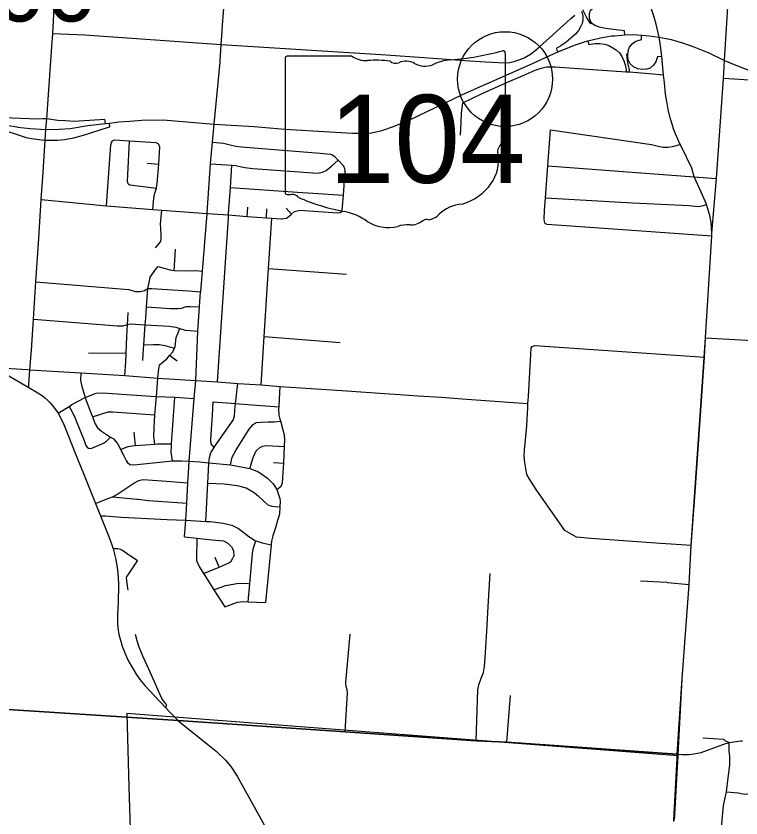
# Model space of a CAD drawing. Extents: x 1659811 to 1934326, y 644115 to 934867.
# Drawn here: x 1837325 to 1848780, y 687199 to 699875 of the extents above; entities that cross this region are included whole.
import ezdxf

# ---------------------------------------------------------------- set-up
doc = ezdxf.new("R2010")
doc.units = 0
for name, color, linetype in [('Default', 7, 'Continuous'), ('GM_X_City_Street', 7, 'Continuous'), ('GM_X_Corporation', 7, 'Continuous'), ('GM_X_County_Road', 7, 'Continuous'), ('GM_X_Interchange_Ramps', 7, 'Continuous'), ('GM_X_State_Route', 7, 'Continuous'), ('GM_X_State_Shield', 7, 'Continuous'), ('GM_X_Township', 7, 'Continuous')]:
    doc.layers.add(name, color=color, linetype=linetype)

msp = doc.modelspace()

# ---------------------------------------------------------------- linework, layer by layer
at = {"layer": 'Default'}
msp.add_circle((1845052, 698878), 750, dxfattribs=at)
at = {"layer": 'GM_X_City_Street'}
for points in [[(1840580, 699632), (1840586, 699731), (1840650, 700535), (1840697, 701240), (1840719, 701531), (1840765, 702254), (1840776, 702431), (1840844, 703924), (1840845, 703934), (1840845, 703937)], [(1837907, 699600), (1837933, 700105), (1837959, 700479), (1837971, 700637), (1837972, 700651)], [(1847992, 691508), (1848048, 692200), (1848097, 692948), (1848203, 694483), (1848221, 694789), (1848318, 696401), (1848321, 696445), (1848310, 696612), (1848289, 696722), (1848236, 696898), (1848234, 696903), (1848131, 697138), (1848040, 697335), (1848004, 697469), (1847840, 697807), (1847820, 697845), (1847746, 698014), (1847716, 698093), (1847691, 698166), (1847661, 698268), (1847628, 698400), (1847607, 698522), (1847590, 698642), (1847572, 698819), (1847558, 698947), (1847530, 699238), (1847515, 699368), (1847504, 699443), (1847487, 699540), (1847436, 699770), (1847403, 699874), (1847339, 700063)], [(1844738, 699151), (1844850, 699144), (1844944, 699139), (1845048, 699135), (1845128, 699143), (1845211, 699161), (1845287, 699186), (1845356, 699215), (1845456, 699275), (1845522, 699324), (1845597, 699389), (1845752, 699530), (1845977, 699730), (1846091, 699834), (1846156, 699888)], [(1837809, 698250), (1837888, 699392), (1837907, 699600)], [(1837907, 699600), (1838413, 699580), (1840566, 699427), (1843171, 699261), (1843771, 699218), (1844419, 699173), (1844738, 699151)], [(1840566, 699427), (1840580, 699632)], [(1840552, 699166), (1840566, 699427)], [(1840165, 694117), (1840200, 694896), (1840226, 695280), (1840242, 695515), (1840243, 695519), (1840269, 695842), (1840344, 696756), (1840345, 696765), (1840396, 697539), (1840397, 697546), (1840429, 697881), (1840456, 698168), (1840551, 699148), (1840552, 699166)], [(1844348, 697993), (1844357, 698196), (1844364, 698341), (1844383, 698503), (1844690, 698650), (1845091, 698828), (1845340, 698936), (1845530, 699021), (1845621, 699053), (1845705, 699072)], [(1845705, 699072), (1845766, 699074), (1845839, 699074), (1846966, 698995), (1847016, 698991)], [(1847016, 698991), (1847329, 698966), (1847558, 698947)], [(1837783, 697914), (1837797, 698083), (1837809, 698250)], [(1845683, 696603), (1845670, 696663), (1845676, 696803), (1845690, 697002), (1845728, 697506), (1845770, 698077)], [(1845770, 698077), (1847365, 697845), (1847473, 697819), (1847553, 697804), (1847631, 697805), (1847697, 697812), (1847820, 697845)], [(1837525, 694003), (1837525, 694057), (1837543, 694284), (1837567, 694593), (1837600, 695085), (1837637, 695675), (1837683, 696361), (1837720, 696974), (1837752, 697400), (1837783, 697914)], [(1838754, 696874), (1838824, 697841), (1838832, 697879), (1838849, 697903)], [(1838849, 697903), (1838883, 697918), (1839115, 697904), (1839535, 697879), (1839575, 697856)], [(1839097, 697225), (1839086, 697262), (1839089, 697364), (1839115, 697904)], [(1839488, 696819), (1839502, 696995), (1839519, 697073), (1839543, 697155), (1839545, 697159), (1839556, 697229), (1839579, 697533), (1839593, 697719), (1839598, 697804), (1839575, 697856)], [(1840429, 697881), (1840602, 697865), (1840710, 697839), (1840798, 697816), (1840886, 697809), (1842130, 697710), (1842288, 697690)], [(1842473, 696787), (1842477, 696809), (1842484, 696865), (1842498, 697045), (1842526, 697430), (1842521, 697458), (1842506, 697502), (1842413, 697599), (1842369, 697644), (1842314, 697681), (1842288, 697690)], [(1840396, 697539), (1840736, 697519), (1840797, 697515), (1840885, 697494), (1840941, 697479), (1841067, 697463), (1842091, 697392), (1842168, 697405), (1842226, 697436), (1842317, 697509), (1842413, 697599)], [(1839398, 697548), (1839579, 697533)], [(1840680, 696688), (1840683, 696731), (1840684, 696752), (1840712, 697164), (1840736, 697519)], [(1845728, 697506), (1848040, 697335), (1848393, 697309)], [(1839097, 697225), (1839121, 697209), (1839543, 697155)], [(1840712, 697164), (1841773, 697092), (1842498, 697045)], [(1837720, 696974), (1838754, 696874), (1839488, 696819), (1839628, 696809), (1840344, 696756), (1840346, 696756), (1840683, 696731), (1840978, 696709), (1841280, 696686), (1841366, 696680), (1841516, 696669), (1841532, 696671)], [(1845690, 697002), (1847065, 696923), (1847964, 696878), (1848102, 696864), (1848188, 696880), (1848236, 696898)], [(1839531, 696209), (1839606, 696304), (1839617, 696344), (1839618, 696406), (1839613, 696520), (1839610, 696586), (1839628, 696809)], [(1840978, 696709), (1840986, 696853)], [(1841280, 696686), (1841290, 696830)], [(1841532, 696671), (1841562, 696677), (1841598, 696683), (1841667, 696734), (1841677, 696743), (1841724, 696788), (1841810, 696807), (1842407, 696766), (1842445, 696771), (1842473, 696787)], [(1841677, 696743), (1841593, 696840)], [(1840510, 694093), (1840680, 696688)], [(1841198, 694046), (1841246, 694808), (1841294, 695559), (1841315, 695886), (1841366, 696680)], [(1845683, 696603), (1845714, 696584), (1845943, 696569), (1848318, 696401)], [(1839837, 696093), (1839837, 696093), (1839843, 696188)], [(1839824, 695855), (1839837, 696093)], [(1839336, 694532), (1839336, 694532), (1839346, 694680), (1839367, 694996), (1839374, 695100), (1839386, 695279), (1839406, 695569), (1839429, 695661), (1839446, 695747), (1839534, 695876), (1839573, 695919)], [(1839573, 695919), (1839660, 695890), (1839782, 695856), (1839824, 695855), (1840050, 695850), (1840162, 695852), (1840269, 695842)], [(1841315, 695886), (1842547, 695797)], [(1837637, 695675), (1838977, 695561), (1839107, 695553), (1839208, 695520), (1839247, 695519), (1839257, 695519)], [(1839257, 695519), (1839290, 695519), (1839353, 695538), (1839406, 695569), (1839471, 695568), (1840052, 695531), (1840242, 695515)], [(1839386, 695279), (1839761, 695255), (1839885, 695251), (1839943, 695258), (1840008, 695283), (1840082, 695286), (1840226, 695280)], [(1839091, 695083), (1839096, 695188)], [(1837600, 695085), (1838927, 694977), (1838940, 694977)], [(1839046, 694193), (1839059, 694405), (1839066, 694545), (1839076, 694809), (1839086, 694999), (1839091, 695079), (1839091, 695083)], [(1838940, 694977), (1838943, 694977), (1839013, 694981), (1839086, 694999), (1839129, 695009), (1839211, 695006), (1839367, 694996), (1839746, 694971), (1839848, 694956), (1839914, 694934), (1839998, 694912), (1840076, 694906), (1840200, 694896)], [(1839516, 693107), (1839500, 693227), (1839505, 693363), (1839518, 693573), (1839542, 693864), (1839565, 694153), (1839580, 694300), (1839594, 694360), (1839706, 694458), (1839750, 694507), (1839805, 694569), (1839827, 694625), (1839837, 694649), (1839857, 694795), (1839884, 694859), (1839914, 694934)], [(1841246, 694808), (1842449, 694714)], [(1848221, 694789), (1849057, 694744), (1849826, 694689), (1850056, 694666), (1850187, 694655), (1850289, 694618), (1850349, 694573), (1850391, 694510), (1850425, 694430), (1850437, 694368), (1850414, 694078), (1850400, 693765)], [(1839346, 694680), (1839490, 694682), (1839593, 694682), (1839678, 694665), (1839752, 694646), (1839827, 694625)], [(1845413, 693751), (1845420, 693862), (1845460, 694532), (1845465, 694624), (1845483, 694654), (1845521, 694669), (1846984, 694568), (1848203, 694483)], [(1838468, 694552), (1839066, 694545)], [(1839329, 694429), (1839336, 694532)], [(1839872, 694418), (1839750, 694507)], [(1836978, 694320), (1837525, 694003), (1837671, 693919), (1837735, 693875), (1837782, 693839), (1837829, 693798), (1837861, 693766), (1837891, 693730), (1837919, 693697), (1837988, 693600), (1838039, 693506), (1838078, 693420), (1838152, 693235), (1838261, 692967), (1838390, 692642), (1838515, 692330), (1838580, 692171), (1838658, 691975), (1838795, 691631), (1838833, 691530), (1838859, 691453), (1838885, 691349), (1838900, 691285), (1838928, 691120), (1838940, 691004), (1838945, 690884), (1838939, 690604), (1838929, 690423), (1838927, 690333), (1838929, 690271), (1838934, 690206), (1838949, 690101), (1838973, 690010), (1839002, 689916), (1839031, 689837), (1839071, 689745), (1839107, 689667), (1839152, 689589), (1839221, 689475), (1839283, 689389), (1839361, 689295), (1839511, 689131), (1839687, 688943), (1839759, 688869), (1839886, 688739)], [(1836978, 694320), (1837505, 694286)], [(1837505, 694286), (1837543, 694284), (1838349, 694235), (1839046, 694193), (1839565, 694153), (1840165, 694117), (1840510, 694093), (1840828, 694069), (1841198, 694046), (1841497, 694017), (1841987, 693988)], [(1838349, 694235), (1838345, 694118), (1838358, 694040), (1838417, 693846), (1838437, 693780), (1838533, 693538), (1838576, 693430), (1838612, 693366), (1838673, 693312), (1838785, 693240), (1838818, 693220), (1838865, 693190), (1838928, 693117), (1838968, 693042), (1838976, 693026), (1839022, 692936), (1839063, 692852), (1839081, 692826), (1839123, 692786)], [(1840044, 692575), (1840049, 692657), (1840063, 692837), (1840138, 693832), (1840165, 694117)], [(1840323, 691887), (1840356, 692494), (1840372, 692805), (1840373, 692814), (1840380, 692899), (1840402, 692971), (1840455, 693057), (1840481, 693100), (1840756, 693487), (1840776, 693552), (1840782, 693644), (1840793, 693749), (1840828, 694069)], [(1841448, 692392), (1841512, 692443), (1841536, 692498), (1841548, 692662), (1841555, 692806), (1841568, 693071), (1841574, 693183), (1841566, 693249), (1841547, 693330), (1841507, 693472), (1841499, 693502), (1841485, 693568), (1841480, 693666), (1841482, 693697), (1841488, 693820), (1841497, 694017)], [(1837988, 693600), (1838164, 693702), (1838209, 693734), (1838417, 693846), (1838592, 693915), (1838692, 693922), (1839535, 693864), (1839542, 693864), (1839832, 693849), (1840138, 693832)], [(1841987, 693988), (1842147, 693979), (1842550, 693953), (1843147, 693910)], [(1843147, 693910), (1843388, 693893), (1843674, 693874)], [(1839795, 692843), (1839775, 692981), (1839781, 693077), (1839783, 693115), (1839832, 693849)], [(1840455, 693057), (1840409, 693113), (1840403, 693183), (1840429, 693572), (1840441, 693777)], [(1840441, 693777), (1840793, 693749), (1841052, 693729), (1841482, 693697)], [(1843674, 693874), (1844049, 693850), (1844374, 693824), (1845183, 693768), (1845413, 693751)], [(1838164, 693702), (1838193, 693657), (1838251, 693544), (1838277, 693476), (1838402, 693164), (1838430, 693088), (1838447, 693062), (1838470, 693044), (1838498, 693040), (1838525, 693043), (1838709, 693126), (1838755, 693158), (1838818, 693220)], [(1847676, 691527), (1847506, 691537), (1846406, 691618), (1846179, 691637), (1845998, 691744), (1845543, 692389), (1845432, 692563), (1845396, 692630), (1845365, 692816), (1845353, 692917), (1845358, 693015), (1845396, 693399), (1845412, 693692), (1845413, 693751)], [(1838533, 693538), (1838778, 693619), (1838854, 693621), (1839518, 693573)], [(1840712, 692781), (1840740, 692902), (1840802, 693020), (1841011, 693346), (1841073, 693418), (1841121, 693448), (1841193, 693455), (1841311, 693459), (1841401, 693459), (1841507, 693472)], [(1839214, 693085), (1839193, 693300)], [(1838976, 693026), (1839094, 693073), (1839158, 693081), (1839214, 693085), (1839516, 693107), (1839562, 693111), (1839783, 693115)], [(1841018, 692725), (1841074, 692899), (1841120, 693001), (1841178, 693054), (1841222, 693076), (1841276, 693086), (1841568, 693071)], [(1839123, 692786), (1839187, 692783), (1839795, 692843), (1839837, 692847), (1839943, 692843), (1840063, 692837), (1840228, 692828), (1840373, 692814), (1840712, 692781), (1841018, 692725), (1841157, 692669), (1841298, 692573), (1841388, 692483), (1841448, 692392), (1841491, 692249)], [(1841391, 692816), (1841555, 692806)], [(1838868, 692287), (1838918, 692311), (1839188, 692492), (1839266, 692534), (1839328, 692551), (1839634, 692526), (1840039, 692497)], [(1839985, 691645), (1840007, 691907), (1840026, 692176), (1840039, 692497), (1840044, 692575)], [(1840356, 692494), (1840615, 692481), (1840818, 692457), (1840962, 692416), (1841086, 692346), (1841157, 692288), (1841235, 692210), (1841301, 692150), (1841367, 692126), (1841420, 692122), (1841495, 692116)], [(1838580, 692171), (1838748, 692240), (1838848, 692277), (1838868, 692287)], [(1838848, 692277), (1839241, 692238), (1839257, 692237)], [(1841491, 692249), (1841497, 692207), (1841495, 692116), (1841486, 692002), (1841458, 691904), (1841423, 691784), (1841383, 691659), (1841361, 691573), (1841354, 691516), (1841267, 690603)], [(1839257, 692237), (1839419, 692220), (1840026, 692176)], [(1838658, 691975), (1838736, 691975), (1838991, 691954), (1839714, 691918), (1840007, 691907)], [(1840007, 691907), (1840323, 691887), (1840391, 691883), (1840598, 691859), (1840734, 691830), (1840838, 691776), (1841003, 691646), (1841109, 691580), (1841115, 691579), (1841215, 691549), (1841354, 691516)], [(1839985, 691645), (1840180, 691622), (1840421, 691595), (1840603, 691578), (1840674, 691543), (1840731, 691486), (1840761, 691427), (1840765, 691343), (1840757, 691319)], [(1840180, 691622), (1840178, 691287), (1840176, 691271), (1840220, 691175), (1840289, 691065), (1840310, 691031), (1840451, 690808), (1840622, 690537)], [(1840991, 690618), (1841017, 690902), (1841060, 691381), (1841071, 691447), (1841088, 691501), (1841115, 691579)], [(1847992, 691508), (1847676, 691527)], [(1847773, 688206), (1847853, 689404), (1847959, 690888), (1847992, 691508)], [(1839095, 690800), (1839088, 690862), (1839073, 690954), (1839068, 690993), (1839076, 691018), (1839094, 691044), (1839244, 691262), (1839080, 691376), (1839006, 691427), (1838976, 691443), (1838933, 691451), (1838859, 691453)], [(1840289, 691065), (1840533, 691163), (1840573, 691179), (1840686, 691232), (1840724, 691257), (1840757, 691319)], [(1840533, 691163), (1840469, 691317)], [(1844769, 690248), (1844787, 690541), (1844815, 691061)], [(1840451, 690808), (1840634, 690874), (1840815, 690903), (1840971, 690909), (1841017, 690902)], [(1847192, 690947), (1847607, 690924), (1847619, 690923)], [(1847619, 690923), (1847959, 690888)], [(1840622, 690537), (1840823, 690610), (1840907, 690623), (1840991, 690618), (1841267, 690603)], [(1844595, 688421), (1844621, 689227), (1844639, 689303), (1844675, 689410), (1844710, 689500), (1844726, 689592), (1844741, 689807), (1844768, 690240), (1844769, 690248)], [(1839687, 688943), (1839707, 688976), (1839698, 689000), (1839654, 689049), (1839630, 689087), (1839586, 689184), (1839505, 689360), (1839421, 689550), (1839333, 689748), (1839270, 689899), (1839241, 689999), (1839214, 690098)], [(1842524, 688560), (1842562, 689176), (1842558, 689226), (1842539, 689278), (1842537, 689343), (1842607, 690105)], [(1845081, 688396), (1845138, 689133)], [(1836126, 688986), (1837200, 688915), (1839886, 688739), (1842524, 688560), (1844595, 688421), (1845081, 688396), (1846201, 688317), (1846717, 688279), (1847773, 688206)], [(1839886, 688739), (1839927, 688705)], [(1839927, 688705), (1840355, 688360), (1840489, 688253), (1840637, 688114), (1840717, 688014), (1840817, 687862), (1841350, 686903), (1841620, 686399), (1841690, 686271), (1841738, 686144), (1841773, 686033), (1841797, 685935), (1841856, 685650), (1841922, 685300), (1842001, 684875), (1842039, 684627), (1842045, 684615)], [(1848175, 688467), (1848503, 688444), (1848525, 688426), (1848595, 688393)], [(1847773, 688206), (1847845, 688202), (1847900, 688202), (1847961, 688205), (1848034, 688212), (1848094, 688222), (1848151, 688233), (1848507, 688364), (1848593, 688392)], [(1848495, 686930), (1848481, 686990), (1848479, 687109), (1848505, 687397), (1848549, 687615), (1848579, 687836), (1848605, 688041), (1848602, 688171), (1848594, 688259), (1848595, 688393)], [(1847771, 688152), (1847772, 688192), (1847773, 688206)], [(1847717, 687141), (1847719, 687167), (1847762, 687948), (1847771, 688152)], [(1848549, 687615), (1848736, 687596), (1848837, 687578), (1848885, 687579), (1849035, 687579), (1849370, 687604), (1849434, 687608), (1849500, 687613), (1849731, 687631), (1849952, 687644), (1849992, 687646), (1850110, 687627), (1850184, 687591), (1850285, 687517), (1850353, 687443), (1850422, 687371), (1850492, 687315), (1850562, 687273), (1850639, 687239), (1850682, 687235), (1850757, 687232)]]:
    msp.add_lwpolyline(points, dxfattribs=at)
at = {"layer": 'GM_X_Corporation'}
msp.add_lwpolyline([(1847728, 687165), (1847787, 688183), (1839078, 688849), (1839109, 687686), (1839160, 686044)], dxfattribs=at)
at = {"layer": 'GM_X_County_Road'}
msp.add_lwpolyline([(1848593, 688392), (1848595, 688393), (1848668, 688402), (1848779, 688417), (1848789, 688416), (1848804, 688416)], dxfattribs=at)
at = {"layer": 'GM_X_Interchange_Ramps'}
for points in [[(1846419, 699762), (1846409, 699754), (1846385, 699785), (1846365, 699815), (1846337, 699860), (1846311, 699911), (1846293, 699953), (1846288, 699972)], [(1846945, 699577), (1846938, 699641), (1846765, 699663), (1846638, 699677), (1846546, 699697), (1846472, 699728), (1846419, 699762), (1846396, 699810), (1846386, 699845), (1846384, 699877), (1846386, 699915), (1846399, 699951), (1846412, 699971), (1846428, 699988), (1846461, 700014), (1846508, 700033), (1846505, 700050)], [(1846258, 699954), (1846266, 699943), (1846281, 699873), (1846281, 699818), (1846268, 699758), (1846244, 699703), (1846215, 699646), (1846164, 699588), (1846094, 699526), (1846017, 699465), (1845932, 699407), (1845862, 699363), (1845884, 699310)], [(1846362, 699486), (1846378, 699424), (1846472, 699439), (1846551, 699439), (1846629, 699431), (1846691, 699409), (1846757, 699375), (1846814, 699337), (1846859, 699292), (1846899, 699235), (1846931, 699167), (1846957, 699090), (1846965, 699027), (1846966, 698995)], [(1847530, 699238), (1847463, 699233), (1847437, 699152), (1847397, 699097), (1847344, 699052), (1847288, 699033), (1847220, 699029), (1847152, 699039), (1847082, 699073), (1847027, 699120), (1846999, 699182), (1846991, 699229), (1846991, 699275), (1847001, 699341), (1847018, 699386), (1847059, 699435), (1847110, 699473), (1847156, 699490), (1847207, 699503), (1847207, 699575)], [(1847016, 698991), (1847016, 699027), (1847007, 699068), (1846999, 699115), (1846989, 699171), (1846980, 699231), (1846978, 699277), (1846991, 699275)], [(1837809, 698250), (1837746, 698251), (1837671, 698247), (1836983, 698269), (1836907, 698274), (1836907, 698274), (1836894, 698208)], [(1838736, 698176), (1838730, 698238), (1838244, 698211), (1838105, 698217), (1837985, 698224), (1837843, 698247), (1837809, 698250)], [(1836998, 698189), (1836990, 698128), (1837045, 698112), (1837147, 698068), (1837326, 698010), (1837486, 697958), (1837567, 697942), (1837652, 697930), (1837726, 697920), (1837783, 697914)], [(1837783, 697914), (1837826, 697911), (1837908, 697914), (1837981, 697914), (1838095, 697924), (1838239, 697950), (1838393, 697992), (1838786, 698118), (1838807, 698122), (1838802, 698184)]]:
    msp.add_lwpolyline(points, dxfattribs=at)
at = {"layer": 'GM_X_State_Route'}
for points in [[(1837337, 698123), (1837355, 698120), (1837549, 698097), (1837797, 698083), (1838008, 698088), (1838180, 698099), (1838460, 698147), (1838736, 698176), (1838802, 698184), (1838950, 698202), (1839123, 698215), (1839313, 698229), (1839649, 698235), (1840456, 698168), (1841086, 698127), (1841574, 698089), (1842285, 698044), (1842644, 698023), (1842768, 698026), (1842941, 698030), (1843103, 698066), (1843290, 698128), (1843550, 698233), (1844378, 698637), (1845484, 699125), (1845884, 699310), (1846166, 699421), (1846293, 699465), (1846362, 699486), (1846562, 699530), (1846732, 699560), (1846785, 699564)], [(1846785, 699564), (1846945, 699577), (1847080, 699582), (1847207, 699575), (1847327, 699565), (1847487, 699540), (1847679, 699502), (1847767, 699479), (1847857, 699451), (1848037, 699391), (1848271, 699295), (1848520, 699171), (1848697, 699099), (1849026, 698973), (1849371, 698873), (1849638, 698825), (1849895, 698797), (1849986, 698787), (1849994, 698783)], [(1833124, 698141), (1833175, 698158), (1833697, 698346), (1833859, 698394), (1833988, 698430), (1834212, 698482), (1834532, 698523), (1834832, 698541), (1835193, 698533), (1835376, 698513), (1835498, 698487), (1836060, 698386), (1836894, 698208), (1836998, 698189), (1837208, 698145), (1837337, 698123)]]:
    msp.add_lwpolyline(points, dxfattribs=at)
at = {"layer": 'GM_X_State_Shield'}
for p, q in [((1842630, 699239), (1841611, 699239)), ((1845057, 698186), (1845057, 699291)), ((1841577, 699203), (1841577, 697089)), ((1845057, 698186), (1845057, 698186))]:
    msp.add_line(p, q, dxfattribs=at)
for centre, major_axis, start_param, end_param in [((1841617, 699207), (40.3, 0), 1.712693, 3.28349), ((1842873, 699484), (391, 0), 4.042523, 4.731795), ((1843817, 702120), (3691, 0), 4.814394, 5.042369), ((1845018, 699296), (38.7, 0), 6.141152, 7.989035), ((1843003, 698053), (1404, 0), 1.404758, 1.657858), ((1843321, 699218), (113, 0), 3.836095, 5.185415), ((1843487, 698974), (235, 0), 0.950623, 2.079405), ((1843790, 699309), (282, 0), 4.081561, 5.145723), ((1844288, 698594), (743, 0), 1.699011, 2.107814), ((1845048, 698105), (60, 0), 1.883978, 3.671073), ((1844667, 697965), (360, 0), 5.934695, 6.695948), ((1845016, 698182), (41.5, 0), 5.05454, 6.418171), ((1845196, 697723), (262, 0), 2.387724, 3.262537), ((1844024, 697583), (923, 0), 5.101752, 6.440018), ((1841617, 697085), (40.7, 0), 3.00124, 4.508301), ((1841623, 697301), (310, 0), 4.665946, 4.897461), ((1841687, 696967), (112, 0), 0.519207, 1.627899), ((1843100, 698866), (2665, 0), 4.195997, 4.488961), ((1844413, 696496), (506, 0), 1.647645, 2.488434), ((1842305, 696140), (834, 0), 0.823519, 1.323587), ((1843773, 696885), (298, 0), 4.937069, 5.64225), ((1843207, 696957), (529, 0), 4.026481, 4.996735), ((1843513, 696226), (435, 0), 1.495662, 1.94098), ((1843551, 696799), (282, 0), 4.691044, 5.507374), ((1843807, 696594), (79.4, 0), 1.147584, 2.315152)]:
    msp.add_ellipse(centre, major_axis=major_axis, ratio=0.8, start_param=start_param, end_param=end_param, dxfattribs=at)
at = {"layer": 'GM_X_Township'}
for points in [[(1849895, 698797), (1848502, 698887), (1848520, 699171), (1848714, 702305)], [(1847728, 687165), (1847787, 688183), (1847788, 688204), (1847850, 689401), (1847959, 690888), (1847991, 691512), (1848200, 694479), (1848221, 694789), (1848318, 696401), (1848321, 696445), (1848393, 697309), (1848502, 698887)], [(1847787, 688183), (1847788, 688204), (1847765, 688206), (1846717, 688279), (1846201, 688317), (1845081, 688396), (1844595, 688421), (1842524, 688560), (1839886, 688739), (1837200, 688915), (1836126, 688986), (1835345, 689037), (1835300, 689039), (1834004, 689124), (1833303, 689177), (1832253, 689251), (1831848, 689276), (1831201, 689315), (1830621, 689354), (1830238, 689382), (1829166, 689438), (1826839, 689523)]]:
    msp.add_lwpolyline(points, dxfattribs=at)

# ---------------------------------------------------------------- texts
at = {"layer": 'Default'}
msp.add_text('10.00', height=1100, dxfattribs=at).set_placement((1834928, 699790))
at = {"layer": 'GM_X_State_Shield'}
msp.add_text('104', height=1392.2, dxfattribs=at).set_placement((1842268, 697238))

doc.saveas('drawing.dxf')
